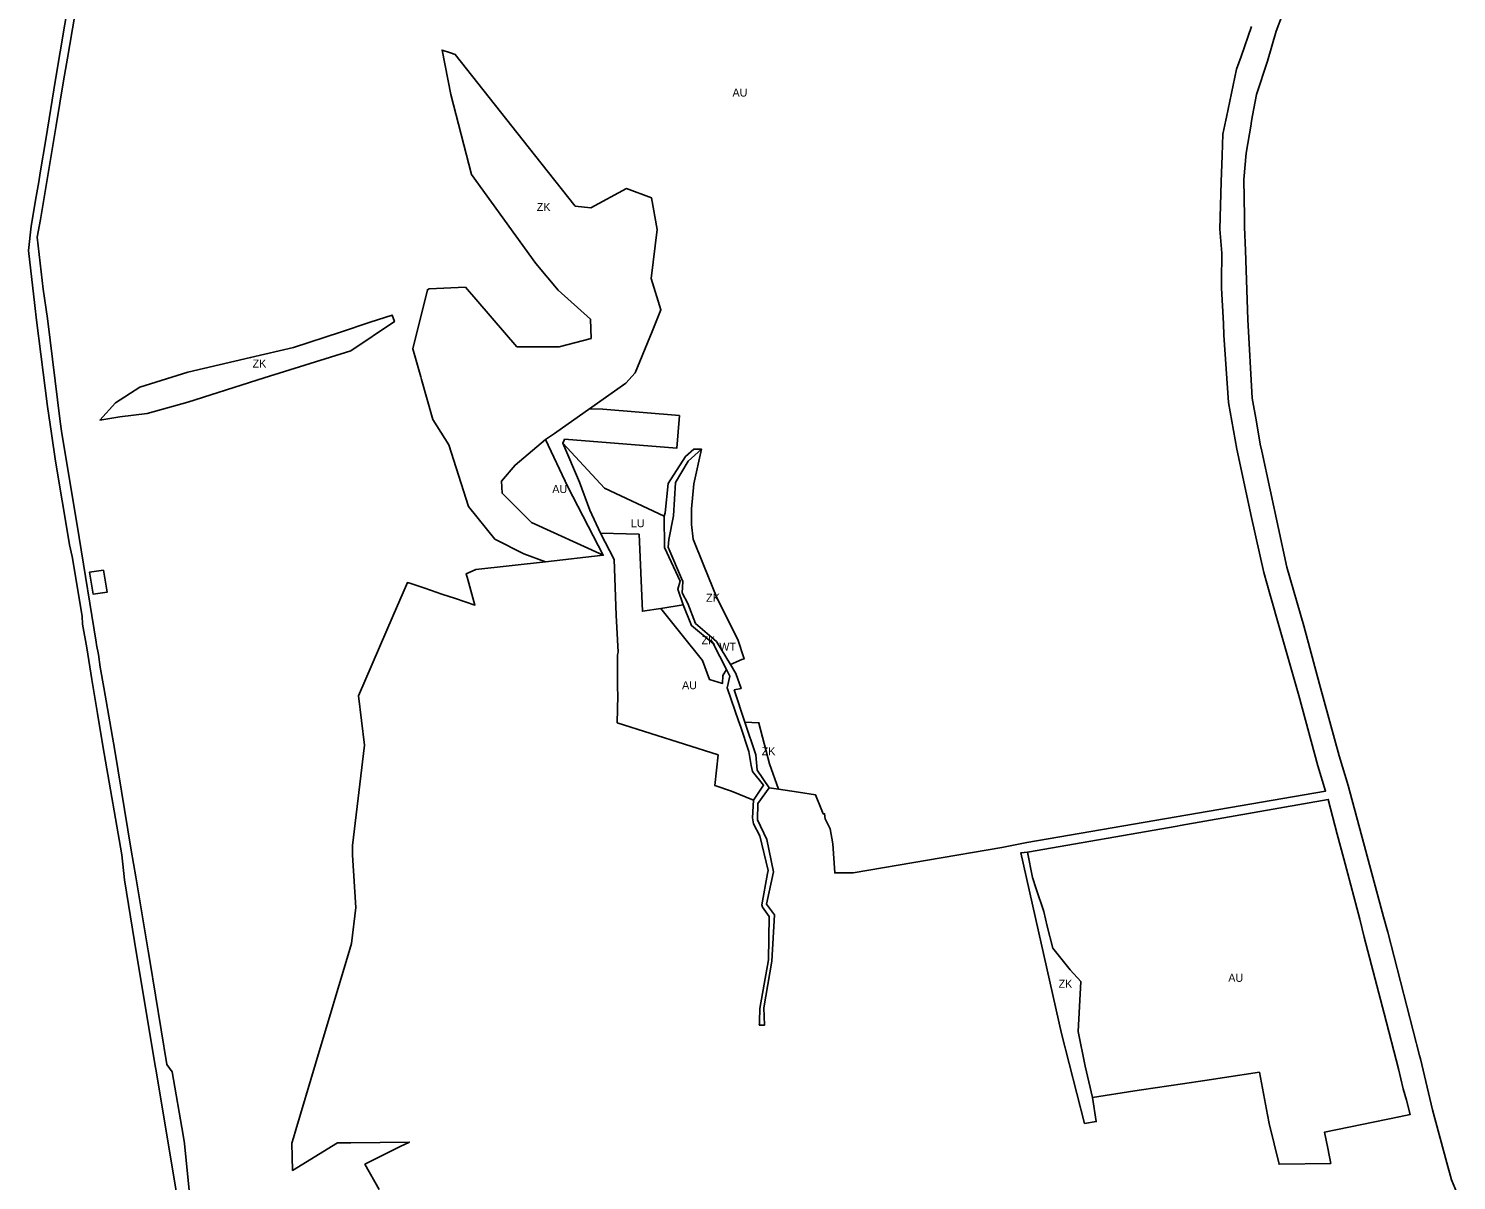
# Model space of a CAD drawing. Extents: x -541351 to -537540, y -1162694 to -1159725.
# Drawn here: x -540396 to -539504, y -1161126 to -1160407 of the extents above; entities that cross this region are included whole.
import ezdxf

# ---------------------------------------------------------------- set-up
doc = ezdxf.new("R2010")
doc.units = 0
for name, color, linetype in [('90640013', 7, 'Continuous'), ('90710013', 7, 'Continuous'), ('90750013', 7, 'Continuous'), ('90770013', 7, 'Continuous')]:
    doc.layers.add(name, color=color, linetype=linetype)

msp = doc.modelspace()

# ---------------------------------------------------------------- linework, layer by layer
at = {"layer": '90640013'}
msp.add_lwpolyline([(-539955.05, -1160819.87), (-539948.394, -1160839.917), (-539941.62, -1160860.32), (-539940.65, -1160870.01), (-539933.13, -1160881.03), (-539940.32, -1160890.74), (-539940.46, -1160901.04), (-539934.74, -1160913.29), (-539930.52, -1160933.46), (-539934.89, -1160953.61), (-539929.8, -1160960.35), (-539931.52, -1160989.33), (-539936.62, -1161018.45), (-539936.15, -1161029.37), (-539936.15, -1161029.37), (-539939.34, -1161029.41), (-539939.29, -1161028.59), (-539939.21, -1161027.06), (-539939.09, -1161018.92), (-539933.67, -1160988.45), (-539933.09, -1160961.38), (-539937.27, -1160955.66), (-539937.85, -1160954.21), (-539934.15, -1160934.56), (-539933.79, -1160932.65), (-539939.03, -1160911.06), (-539942.93, -1160903.55), (-539943.56, -1160899.72), (-539943.03, -1160888.81), (-539936.68, -1160879.28), (-539943.7, -1160870.89), (-539944.35, -1160866.97), (-539945.91, -1160858.23), (-539951.15, -1160842.57), (-539952.118, -1160839.729), (-539959.33, -1160818.58), (-539957.74, -1160811.35), (-539959.908, -1160807.042), (-539968.08, -1160790.81), (-539981.63, -1160779.68), (-539986.83, -1160766.76), (-539990.3, -1160756.79), (-539988.79, -1160751.87), (-539998.62, -1160730.92), (-539998.88, -1160711.28), (-539998.13, -1160709.19), (-539996.34, -1160690.78), (-539985.54, -1160673.96), (-539980.29, -1160669.52), (-539975.53, -1160669.32), (-539983.78, -1160676.86), (-539991.63, -1160690.18), (-539993.04, -1160711.11), (-539995.79, -1160725.79), (-539996.27, -1160730.67), (-539995.18, -1160733.22), (-539988.6, -1160748.68), (-539987.15, -1160752.09), (-539987.59, -1160759.2), (-539984.04, -1160765.87), (-539979.29, -1160778.28), (-539966.11, -1160789.54), (-539957.27, -1160804.046), (-539957.27, -1160804.046), (-539953.94, -1160809.51), (-539950.7, -1160819.03)], close=True, dxfattribs=at)
at = {"layer": '90710013'}
for points in [[(-540006.699, -1160512.43), (-540003.075, -1160532.185), (-540006.82, -1160562.734), (-540000.86, -1160582.31), (-540000.86, -1160582.31), (-540006.23, -1160595.9), (-540016.83, -1160621.72), (-540022.71, -1160628.19), (-540065.89, -1160658.49), (-540067.41, -1160659.58), (-540072.96, -1160663.43), (-540091.947, -1160679.324), (-540100.479, -1160689.433), (-540100.102, -1160696.968), (-540081.627, -1160715.24), (-540036.88, -1160735.75), (-540072.855, -1160739.734), (-540086.367, -1160734.818), (-540104.555, -1160725.719), (-540121.015, -1160705.298), (-540133.36, -1160666.761), (-540143.269, -1160650.796), (-540150.39, -1160625.84), (-540150.87, -1160624.16), (-540155.873, -1160606.628), (-540146.72, -1160569.77), (-540145.68, -1160569.15), (-540122.99, -1160568.3), (-540090.77, -1160605.52), (-540064.4, -1160605.52), (-540044.48, -1160600.22), (-540044.86, -1160588.28), (-540064.98, -1160570.08), (-540078.88, -1160553.44), (-540119.13, -1160497.83), (-540131.98, -1160447.76), (-540137.57, -1160420.03), (-540132.3, -1160421.84), (-540129.29, -1160422.87), (-540079.74, -1160485.429), (-540079.74, -1160485.429), (-540054.348, -1160517.487), (-540044.554, -1160518.64), (-540022.38, -1160506.633)], [(-540321.848, -1160647.163), (-540338.81, -1160649.12), (-540351.335, -1160651.224), (-540341.491, -1160640.464), (-540326.39, -1160630.682), (-540296.336, -1160621.314), (-540257.199, -1160612.227), (-540230.367, -1160605.997), (-540201.022, -1160596.302), (-540182.409, -1160590.152), (-540168.651, -1160585.607), (-540167.37, -1160589.73), (-540194.618, -1160607.889), (-540248.688, -1160624.938), (-540296.406, -1160639.984)], [(-539948.906, -1160800.463), (-539950.199, -1160800.762), (-539957.27, -1160804.046), (-539966.11, -1160789.54), (-539979.29, -1160778.28), (-539984.04, -1160765.87), (-539987.59, -1160759.2), (-539987.15, -1160752.09), (-539988.6, -1160748.68), (-539995.18, -1160733.22), (-539996.269, -1160730.665), (-539995.79, -1160725.79), (-539993.04, -1160711.11), (-539991.63, -1160690.18), (-539983.78, -1160676.86), (-539975.53, -1160669.32), (-539980.245, -1160691.056), (-539981.656, -1160706.718), (-539981.68, -1160716.428), (-539980.594, -1160725.578), (-539974.192, -1160741.591), (-539965.727, -1160762.765), (-539952.724, -1160788.409)], [(-539959.908, -1160807.042), (-539962.082, -1160810.762), (-539962.322, -1160815.831), (-539970.494, -1160813.368), (-539974.901, -1160801.514), (-539988.398, -1160784.552), (-540000.842, -1160768.913), (-539986.83, -1160766.76), (-539981.63, -1160779.68), (-539968.08, -1160790.81)], [(-539948.394, -1160839.917), (-539939.607, -1160840.361), (-539939.556, -1160840.615), (-539932.972, -1160865.976), (-539927.316, -1160881.911), (-539933.13, -1160881.03), (-539940.65, -1160870.01), (-539941.62, -1160860.32)], [(-539736.18, -1161090.79), (-539750.503, -1161034.411), (-539775.88, -1160921.568), (-539771.7, -1160921.26), (-539768.71, -1160937.12), (-539766.36, -1160944.07), (-539761.54, -1160958.34), (-539759.45, -1160967.35), (-539756.04, -1160981.27), (-539745.1, -1160994.72), (-539738.55, -1161002.02), (-539740.05, -1161033.33), (-539735.79, -1161055.02), (-539731.15, -1161074.48), (-539728.84, -1161089.57)]]:
    msp.add_lwpolyline(points, close=True, dxfattribs=at)
at = {"layer": '90750013'}
for points in [[(-540367.38, -1160369.03), (-540379.07, -1160438.35), (-540385.21, -1160475.93), (-540388.61, -1160496.72), (-540389.59, -1160502.47), (-540391.13, -1160511.56), (-540394.19, -1160530.11), (-540395.91, -1160545.34), (-540391.97, -1160579.55), (-540390.89, -1160588.89), (-540388.21, -1160610), (-540384.03, -1160642.85), (-540381.66, -1160659.6), (-540379.03, -1160677.01), (-540370.76, -1160726.58), (-540370.43, -1160729.11), (-540368.65, -1160736.51), (-540362.4, -1160773.82), (-540362.13, -1160778.82), (-540359.51, -1160793.49), (-540356.38, -1160813.29), (-540352.78, -1160834.49), (-540351.34, -1160843.57), (-540348.66, -1160859.5), (-540337.58, -1160922.86), (-540336.04, -1160938.56), (-540328.53, -1160984.68), (-540316.56, -1161055.73), (-540316.41, -1161056.82), (-540301.95, -1161142.81)], [(-540294.74, -1161140.88), (-540298.48, -1161103.29), (-540299.4, -1161097.97), (-540306.26, -1161058.41), (-540309.59, -1161053.9), (-540320.11, -1160989), (-540321.15, -1160982.89), (-540328.9, -1160936.63), (-540331.73, -1160920.05), (-540342.08, -1160857.75), (-540348.88, -1160818.39), (-540351.12, -1160805.53), (-540352.31, -1160797.72), (-540353.36, -1160791.66), (-540353.65, -1160790.09), (-540364.34, -1160724.7), (-540375.43, -1160658.17), (-540376.23, -1160652.23), (-540384.15, -1160587.81), (-540386.78, -1160569.5), (-540390.49, -1160537.06), (-540388.47, -1160525.94), (-540378.74, -1160467.09), (-540374.16, -1160439.26), (-540371.68, -1160425.08), (-540361.01, -1160362.65)], [(-539503.79, -1161133.46), (-539506.91, -1161125.99), (-539509.83, -1161115.28), (-539518.85, -1161082.11), (-539526.32, -1161050.29), (-539526.79, -1161048.34), (-539546.7, -1160971.15), (-539549.36, -1160961.61), (-539571.49, -1160879.49), (-539576.96, -1160860.94), (-539589.32, -1160816.2), (-539599.23, -1160779.87), (-539609.66, -1160743.12), (-539625.46, -1160670.68), (-539626.36, -1160666.27), (-539628.8, -1160652.38), (-539631.37, -1160637.5), (-539634.2, -1160588.33), (-539635.66, -1160545.36), (-539636.18, -1160530.77), (-539636.18, -1160524.12), (-539636.65, -1160500.97), (-539635.21, -1160484.43), (-539632.14, -1160466.29), (-539632.01, -1160465.71), (-539631.19, -1160460.88), (-539628.67, -1160447.82), (-539621.83, -1160426.91), (-539616.32, -1160408.3), (-539612.5, -1160397.88)], [(-539631.8, -1160405.4), (-539638.38, -1160424.12), (-539641.15, -1160432), (-539644.34, -1160446.97), (-539647.54, -1160461.93), (-539647.95, -1160463.89), (-539649.83, -1160472.69), (-539650.25, -1160485.84), (-539650.77, -1160502.39), (-539651.71, -1160531.92), (-539650.35, -1160547.02), (-539650.41, -1160548.28), (-539650.6, -1160563.3), (-539650.68, -1160568.9), (-539649.42, -1160590.92), (-539649.14, -1160598.17), (-539646.24, -1160640.35), (-539641.09, -1160669.51), (-539631.78, -1160712.13), (-539624.15, -1160746.4), (-539620.46, -1160759.86), (-539613.99, -1160782.56), (-539603.06, -1160820.51), (-539602.29, -1160823.36), (-539590.37, -1160867.23), (-539585.53, -1160883.06), (-539772.26, -1160915.27), (-539787.89, -1160918.34), (-539880.8, -1160934.07), (-539892.26, -1160934.14), (-539892.26, -1160934.14), (-539893.45, -1160916), (-539895.16, -1160906.55), (-539898.14, -1160900.32), (-539898.55, -1160897.19), (-539899.39, -1160897.3), (-539900.72, -1160894.08), (-539904.22, -1160885.41), (-539914.91, -1160883.79), (-539927.316, -1160881.911), (-539932.972, -1160865.976), (-539939.556, -1160840.615), (-539939.607, -1160840.361), (-539948.394, -1160839.917), (-539955.05, -1160819.87), (-539950.7, -1160819.03), (-539953.94, -1160809.51), (-539957.27, -1160804.046), (-539957.27, -1160804.046), (-539950.199, -1160800.762), (-539948.906, -1160800.463), (-539952.724, -1160788.409), (-539965.727, -1160762.765), (-539974.192, -1160741.591), (-539980.594, -1160725.578), (-539981.68, -1160716.428), (-539981.656, -1160706.718), (-539980.245, -1160691.056), (-539975.53, -1160669.32), (-539980.29, -1160669.52), (-539985.54, -1160673.96), (-539996.34, -1160690.78), (-539998.13, -1160709.19), (-539998.88, -1160711.28), (-540036, -1160693.7), (-540062.12, -1160665.66), (-540061.35, -1160663.86), (-540060.96, -1160663.22), (-539990.815, -1160668.698), (-539990.815, -1160668.698), (-539989.236, -1160648.407), (-540037.21, -1160644.48), (-540045.415, -1160644.122), (-540045.415, -1160644.122), (-540022.71, -1160628.19), (-540016.83, -1160621.72), (-540006.23, -1160595.9), (-540000.86, -1160582.31), (-540000.86, -1160582.31), (-540006.82, -1160562.734), (-540003.075, -1160532.185), (-540006.699, -1160512.43), (-540022.38, -1160506.633), (-540044.554, -1160518.64), (-540054.348, -1160517.487), (-540079.74, -1160485.429), (-540079.74, -1160485.429), (-540129.29, -1160422.87), (-540132.3, -1160421.84), (-540137.57, -1160420.03), (-540131.98, -1160447.76), (-540119.13, -1160497.83), (-540078.88, -1160553.44), (-540064.98, -1160570.08), (-540044.86, -1160588.28), (-540044.48, -1160600.22), (-540064.4, -1160605.52), (-540090.77, -1160605.52), (-540122.99, -1160568.3), (-540145.68, -1160569.15), (-540146.72, -1160569.77), (-540155.873, -1160606.628), (-540155.873, -1160606.628), (-540150.87, -1160624.16), (-540150.39, -1160625.84), (-540143.269, -1160650.796), (-540133.36, -1160666.761), (-540121.015, -1160705.298), (-540104.555, -1160725.719), (-540086.367, -1160734.818), (-540072.855, -1160739.734), (-540116.53, -1160744.57), (-540122.56, -1160747.33), (-540121.54, -1160750.93), (-540117.04, -1160766.9), (-540129.12, -1160762.82), (-540137.65, -1160759.94), (-540148.41, -1160756.31), (-540157.05, -1160753.39), (-540159.21, -1160752.73), (-540159.87, -1160754.25), (-540168.1, -1160773.35), (-540189.73, -1160823.53), (-540186.01, -1160854.27), (-540193.55, -1160916.96), (-540193.61, -1160923), (-540191.36, -1160955.77), (-540194.2, -1160978.35), (-540195.22, -1160981.77), (-540216.63, -1161053.39), (-540228.99, -1161094.76), (-540230.48, -1161099.76), (-540231.49, -1161103.13), (-540230.96, -1161120.03), (-540202.91, -1161102.9), (-540194.5, -1161102.8), (-540157.96, -1161102.34), (-540163.73, -1161105.11), (-540185.73, -1161116.2), (-540176.86, -1161131.88)]]:
    msp.add_lwpolyline(points, dxfattribs=at)
for points in [[(-540194.618, -1160607.889), (-540167.37, -1160589.73), (-540168.651, -1160585.607), (-540182.409, -1160590.152), (-540201.022, -1160596.302), (-540230.367, -1160605.997), (-540257.199, -1160612.227), (-540296.336, -1160621.314), (-540326.39, -1160630.682), (-540341.491, -1160640.464), (-540351.335, -1160651.224), (-540338.81, -1160649.12), (-540321.848, -1160647.163), (-540296.406, -1160639.984), (-540248.688, -1160624.938)], [(-540072.96, -1160663.43), (-540059.03, -1160692.85), (-540036.88, -1160735.75), (-540081.627, -1160715.24), (-540100.102, -1160696.968), (-540100.479, -1160689.433), (-540091.947, -1160679.324)], [(-539965.12, -1160860.37), (-540028.13, -1160840.36), (-540027.8, -1160823.41), (-540027.93, -1160818.42), (-540027.93, -1160818.42), (-540027.87, -1160797.94), (-540027.5, -1160796.19), (-540028.72, -1160773.19), (-540030.03, -1160738.43), (-540038.55, -1160721.9), (-540014.46, -1160722.6), (-540012.41, -1160770.69), (-540000.842, -1160768.913), (-539988.398, -1160784.552), (-539974.901, -1160801.514), (-539970.494, -1160813.368), (-539962.322, -1160815.831), (-539962.082, -1160810.762), (-539959.908, -1160807.042), (-539957.74, -1160811.35), (-539959.33, -1160818.58), (-539952.118, -1160839.729), (-539951.15, -1160842.57), (-539945.91, -1160858.23), (-539944.35, -1160866.97), (-539943.7, -1160870.89), (-539936.68, -1160879.28), (-539943.03, -1160888.81), (-539956.82, -1160883.15), (-539967.05, -1160879.62)], [(-540349.01, -1160744.97), (-540357.81, -1160746.26), (-540355.54, -1160760.09), (-540346.71, -1160758.68)], [(-539534.97, -1161076.16), (-539532.67, -1161085.08), (-539539.6, -1161086.5), (-539586.15, -1161096.06), (-539583.98, -1161107.12), (-539583.51, -1161109.53), (-539582.3, -1161115.66), (-539614.61, -1161116.17), (-539620.86, -1161090.73), (-539621.9, -1161085.23), (-539626.91, -1161058.7), (-539648.73, -1161061.97), (-539660.98, -1161063.8), (-539674.91, -1161065.89), (-539700.61, -1161069.8), (-539704.64, -1161070.36), (-539731.15, -1161074.48), (-539735.79, -1161055.02), (-539740.05, -1161033.33), (-539738.55, -1161002.02), (-539745.1, -1160994.72), (-539756.04, -1160981.27), (-539759.45, -1160967.35), (-539761.54, -1160958.34), (-539766.36, -1160944.07), (-539768.71, -1160937.12), (-539771.7, -1160921.26), (-539678.23, -1160904.87), (-539676.35, -1160904.54), (-539583.93, -1160888.29), (-539578.21, -1160910), (-539574.11, -1160925.41), (-539571.68, -1160934.67), (-539564.23, -1160963.09), (-539561.45, -1160974.35), (-539548.91, -1161021.98), (-539539.99, -1161056.65), (-539536.99, -1161068.99)]]:
    msp.add_lwpolyline(points, close=True, dxfattribs=at)
at = {"layer": '90770013'}
msp.add_lwpolyline([(-540051.73, -1160690.03), (-540062.12, -1160665.66), (-540036, -1160693.7), (-539998.88, -1160711.28), (-539998.62, -1160730.92), (-539988.79, -1160751.87), (-539990.3, -1160756.79), (-539986.83, -1160766.76), (-540000.842, -1160768.913), (-540012.41, -1160770.69), (-540014.46, -1160722.6), (-540038.55, -1160721.9), (-540045.29, -1160707.57)], close=True, dxfattribs=at)

# ---------------------------------------------------------------- texts
at = {"layer": '90640013'}
msp.add_text('WT', height=5, rotation=0, dxfattribs=at).set_placement((-539964.34, -1160795.342))
at = {"layer": '90710013'}
for rotation, p in [(0, (-540078.366, -1160520.609)), (0, (-540255.927, -1160618.416)), (360, (-539972.588, -1160764.805)), (360, (-539975.434, -1160791.295)), (0, (-539937.855, -1160860.636)), (0, (-539752.36, -1161005.974))]:
    msp.add_text('ZK', height=5, rotation=rotation, dxfattribs=at).set_placement(p)
at = {"layer": '90750013'}
for rotation, p in [(0, (-539956.105, -1160449.125)), (360, (-540068.679, -1160696.822)), (360, (-539987.615, -1160819.381)), (360, (-539646.335, -1161002.23))]:
    msp.add_text('AU', height=5, rotation=rotation, dxfattribs=at).set_placement(p)
at = {"layer": '90770013'}
msp.add_text('LU', height=5, rotation=0, dxfattribs=at).set_placement((-540019.545, -1160718.175))

doc.saveas('drawing.dxf')
